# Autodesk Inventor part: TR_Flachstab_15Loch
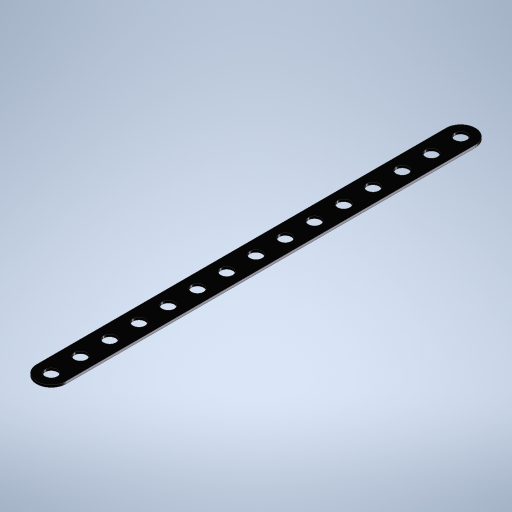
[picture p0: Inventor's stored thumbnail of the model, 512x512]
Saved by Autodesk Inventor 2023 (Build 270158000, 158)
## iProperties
Created: 2023-11
Part Number: TR_Flachstab_15Loch
Material: Edelstahl
Document SubType Name: Modeling
Designer: Admin
Density: 8 g/cm^3
Appearance: Halbpoliert
Author: Admin
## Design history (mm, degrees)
sketch "Skizze1"
  geometry: L1 (0, 70)-(0, -70); L2 (-5, 70)-(-5, -70); L3 (5, -70)-(5, 70); A1 r 5 centre (0, 70) between (5, 70) and (-5, 70); A2 r 5 centre (0, -70) between (-5, -70) and (5, -70); 3 further points
  constraints: 8 end point, 4 point on circle, 4 tangent, 2 centre point, 2 midpoint, 1 horizontal alignment, 1 parallel, 1 vertical, 1 vertical alignment
  dimensions: "d0" = 140 distance of L1.start L1.end (computed from Loch, Einheitsmaß); "d1" = 5 radius of A1 (= 0.5 x Einheitsmaß)
extrude "Extrusion1" new body sketch "Skizze1" distance "d5" = 0.8 (= Dicke); taper "d6" = 0 deg
sketch "Skizze2"
  geometry: C1 r 2.075 at (0, 70); A1 r 5 centre (0, 70) between (5, 70) and (-5, 70) reference; 1 further point
  constraints: 1 centre point, 1 coincident
  dimensions: "d7" = 4.15 diameter of C1 (= 2 x Radius)
extrude "Extrusion2" cut sketch "Skizze2" stored distance "d8" = 10; taper "d9" = 0 deg
pattern_linear "Rechteckige Anordnung1" dims "d12" = 10 (= Einheitsmaß)
node "Volumenkörper1"
other parameters: "Einheitsmaß" = 10 [user parameter; used in 3 equation terms], "Radius" = 2.075 [user parameter; used in 1 equation term], "Fasen" = 0.5 [user parameter], "Dicke" = 0.8 [user parameter; used in 1 equation term]
